// Mitsubishi GX Works2 project: 练习000_FX3U与台达变频器VFD-M通信   PLC: FX3U/FX3UC

PROGRAM MAIN
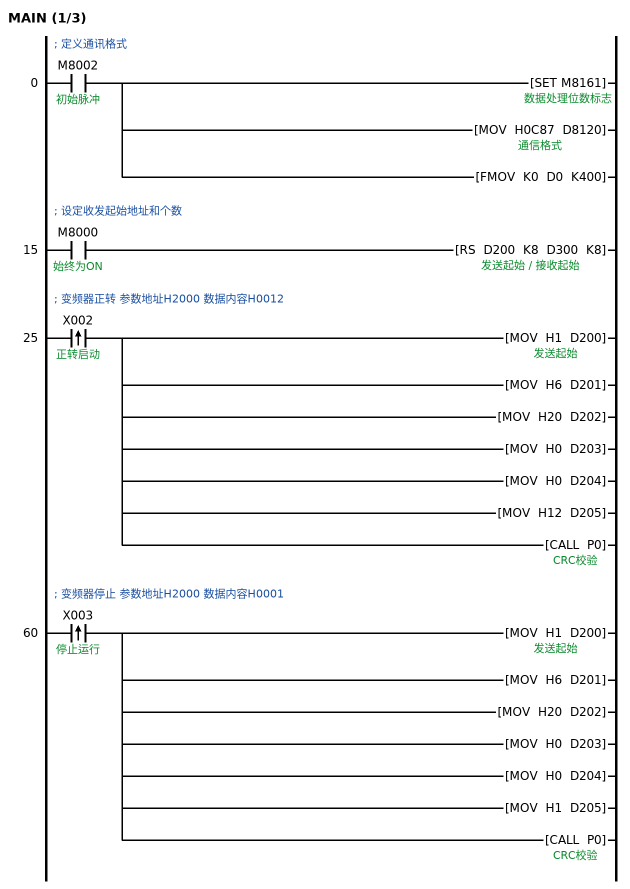
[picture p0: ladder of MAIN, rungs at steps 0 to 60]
; 定义通讯格式
0     LD      M8002  ; 初始脉冲
      SET     M8161  ; 数据处理位数标志
        [note] 处理低8位数据
      MOV     H0C87 D8120  ; 通信格式
        [note] 波特率9600b/s，数据格式8  E  1
      FMOV    K0 D0 K400
        [note] 批量清零寄存器
; 设定收发起始地址和个数
15    LD      M8000  ; 始终为ON
      RS      D200 K8 D300 K8  ; 发送起始 / 接收起始
        [note] 收发数据起始地址和个数
; 变频器正转 参数地址H2000 数据内容H0012
25    LDP     X002  ; 正转启动
      MOV     H1 D200
        [note] 写入从站站号
      MOV     H6 D201
        [note] 写入功能码
      MOV     H20 D202
        [note] 写入参数地址 高8位
      MOV     H0 D203
        [note] 写入参数地址 低8位
      MOV     H0 D204
        [note] 写入数据内容 高8位
      MOV     H12 D205
        [note] 写入数据内容 低8位
      CALL    P0  ; CRC校验
; 变频器停止 参数地址H2000 数据内容H0001
60    LDP     X003  ; 停止运行
      MOV     H1 D200
        [note] 写入从站站号
      MOV     H6 D201
        [note] 写入功能码
      MOV     H20 D202
        [note] 写入参数地址 高8位
      MOV     H0 D203
        [note] 写入参数地址 低8位
      MOV     H0 D204
        [note] 写入数据内容 高8位
      MOV     H1 D205
        [note] 写入数据内容 低8位
      CALL    P0
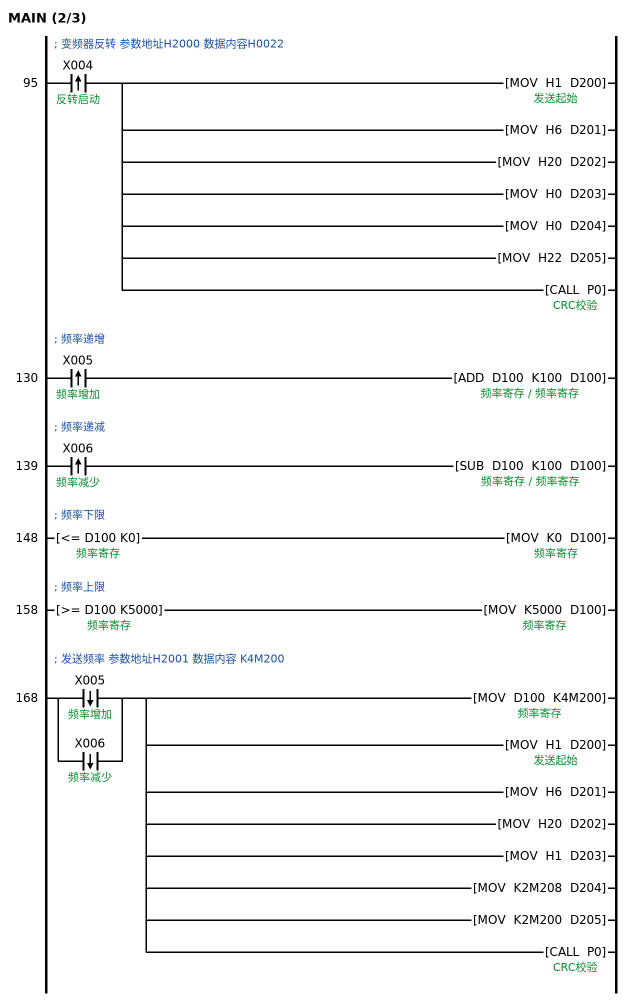
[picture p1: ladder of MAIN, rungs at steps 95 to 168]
; 变频器反转 参数地址H2000 数据内容H0022
95    LDP     X004  ; 反转启动
      MOV     H1 D200
        [note] 写入从站站号
      MOV     H6 D201
        [note] 写入功能码
      MOV     H20 D202
        [note] 写入参数地址 高8位
      MOV     H0 D203
        [note] 写入参数地址 低8位
      MOV     H0 D204
        [note] 写入数据内容 高8位
      MOV     H22 D205
        [note] 写入数据内容 低8位
      CALL    P0
; 频率递增
130   LDP     X005  ; 频率增加
      ADD     D100 K100 D100  ; 频率寄存
        [note] 频率递增
; 频率递减
139   LDP     X006  ; 频率减少
      SUB     D100 K100 D100
        [note] 频率递减
; 频率下限
148   LD<=    D100 K0  ; 频率寄存
      MOV     K0 D100
        [note] 频率下限
; 频率上限
158   LD>=    D100 K5000  ; 频率寄存
      MOV     K5000 D100
        [note] 频率上限
; 发送频率 参数地址H2001 数据内容 K4M200
168   LDF     X005  ; 频率增加
      ORF     X006  ; 频率减少
      MOV     D100 K4M200
        [note] 写入频率寄存
      MOV     H1 D200
        [note] 写入从站站号
      MOV     H6 D201
        [note] 写入功能码
      MOV     H20 D202
        [note] 写入参数地址 高8位
      MOV     H1 D203
        [note] 写入参数地址 低8位
      MOV     K2M208 D204
        [note] 写入数据内容 高8位
      MOV     K2M200 D205
        [note] 写入数据内容 低8位
      CALL    P0
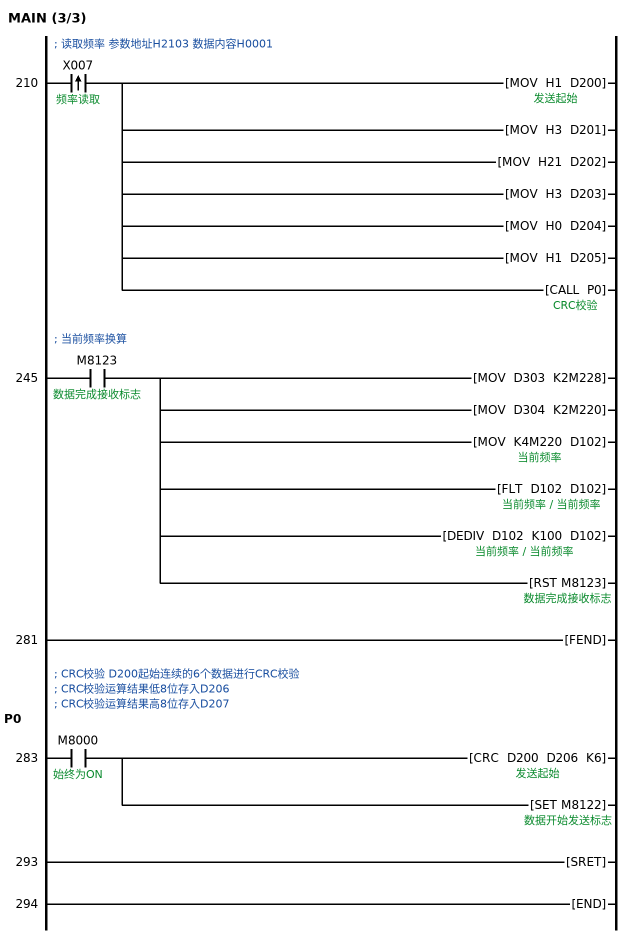
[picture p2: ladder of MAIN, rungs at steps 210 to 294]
; 读取频率 参数地址H2103 数据内容H0001
210   LDP     X007  ; 频率读取
      MOV     H1 D200
        [note] 写入从站站号
      MOV     H3 D201
        [note] 写入功能码
      MOV     H21 D202
        [note] 写入参数地址 高8位
      MOV     H3 D203
        [note] 写入参数地址 低8位
      MOV     H0 D204
        [note] 写入数据内容 高8位
      MOV     H1 D205
        [note] 写入数据内容 低8位
      CALL    P0
; 当前频率换算
245   LD      M8123  ; 数据完成接收标志
      MOV     D303 K2M228
        [note] 接收频率的高8位
      MOV     D304 K2M220
        [note] 接收频率的低8位
      MOV     K4M220 D102  ; 当前频率
        [note] 接收频率合成16位
      FLT     D102 D102
        [note] 二进制整数转换浮点数
      DEDIV   D102 K100 D102
        [note] 转换为当前频率
      RST     M8123  ; 数据完成接收标志
281   FEND
        [note] 主程序结束
; CRC校验 D200起始连续的6个数据进行CRC校验
; CRC校验运算结果低8位存入D206
; CRC校验运算结果高8位存入D207
      P0
283   LD      M8000  ; 始终为ON
      CRC     D200 D206 K6
        [note] CRC校验
      SET     M8122  ; 数据开始发送标志
293   SRET
        [note] 子程序结束
294   END
END_PROGRAM

// device comments not shown above
Y000  ; 正转输出
Y001  ; 反转输出
Y002  ; 3#输出
Y003  ; 1#反向
Y004  ; 2#方向
Y005  ; 3#反向
M0  ; 运行标识
M1  ; 回原标识
M2  ; 2#正JOG
M3  ; 2#反JOG
M4  ; 3#正JOG
M5  ; 3#反JOG
M6  ; 1#清零
M7  ; 2#清零
M8  ; 3#清零
M10  ; 运行标志
M30  ; 回原标志
D10  ; 步转换
D20  ; 累计脉冲
D22  ; 累计脉冲
D214  ; 2#频率
D224  ; 3#频率
D310  ; 2#当前值
D320  ; 3#当前值
X014  ; 启动按钮
X015  ; 回原按钮
C251  ; 当前脉冲
T0  ; 计时5s
T1  ; 计时5s
